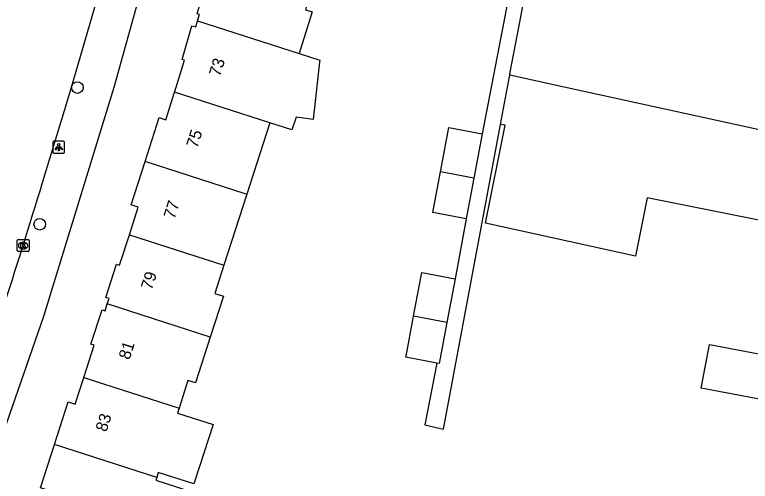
# Model space of a CAD drawing. Extents: x 161402 to 161933, y 381650 to 382313.
# Drawn here: x 161765.1 to 161827.2, y 381716.7 to 381756.1 of the extents above; entities that cross this region are included whole.
import ezdxf

# ---------------------------------------------------------------- set-up
doc = ezdxf.new("R2010")
doc.units = 0
for name, color, linetype in [('IMGEO_Boom', 7, 'Continuous'), ('IMGEO_Kolk', 7, 'Continuous'), ('IMGEO_Lichtpunt', 7, 'Continuous'), ('IMGEO_Pand', 7, 'Continuous'), ('IMGEO_Pand_nummerreeks', 7, 'Continuous'), ('IMGEO_Rijbaan_lokaal_open', 7, 'Continuous'), ('IMGEO_Voetpad_open', 7, 'Continuous')]:
    doc.layers.add(name, color=color, linetype=linetype)

msp = doc.modelspace()

# ---------------------------------------------------------------- linework, layer by layer
at = {"layer": 'IMGEO_Boom'}
for centre in [(161770.361, 381749.955), (161767.179, 381738.411)]:
    msp.add_circle(centre, 0.489, dxfattribs=at)
at = {"layer": 'IMGEO_Kolk'}
for p, q in [((161765.273, 381736.185), (161765.273, 381737.037)), ((161765.348, 381737.111), (161766.2, 381737.111)), ((161765.761, 381736.891), (161765.786, 381736.891)), ((161766.274, 381737.037), (161766.274, 381736.185)), ((161766.2, 381736.111), (161765.348, 381736.111)), ((161765.784, 381736.331), (161765.759, 381736.331))]:
    msp.add_line(p, q, dxfattribs=at)
for points in [[(161765.273, 381736.185), (161765.273, 381737.037)], [(161765.348, 381737.111), (161766.2, 381737.111)], [(161765.594, 381736.811), (161765.717, 381736.811), (161765.717, 381736.66), (161765.847, 381736.811), (161766.011, 381736.811), (161765.865, 381736.66), (161766.018, 381736.411), (161765.866, 381736.411), (161765.781, 381736.575), (161765.717, 381736.508), (161765.717, 381736.411), (161765.594, 381736.411), (161765.594, 381736.811)], [(161766.274, 381737.037), (161766.274, 381736.185)], [(161766.2, 381736.111), (161765.348, 381736.111)]]:
    msp.add_lwpolyline(points, dxfattribs=at)
for centre, start, end in [((161765.35, 381737.035), 91.55205, 178.44795), ((161765.35, 381737.035), 91.55205, 178.44795), ((161766.198, 381737.035), 1.55205, 88.44795), ((161766.198, 381737.035), 1.55205, 88.44795), ((161765.35, 381736.187), 181.55205, 268.44795), ((161765.35, 381736.187), 181.55205, 268.44795), ((161766.198, 381736.187), 271.55205, 358.44795), ((161766.198, 381736.187), 271.55205, 358.44795)]:
    msp.add_arc(centre, 0.0765, start, end, dxfattribs=at)
for centre, major_axis, ratio, start_param, end_param in [((161765.76, 381736.611), (-0.387, 0.002), 0.722429, 4.712389, 7.853982), ((161765.785, 381736.611), (-0.39, 0.002), 0.717154, 1.570796, 4.712389)]:
    msp.add_ellipse(centre, major_axis=major_axis, ratio=ratio, start_param=start_param, end_param=end_param, dxfattribs=at)
at = {"layer": 'IMGEO_Lichtpunt'}
for p, q in [((161769.19, 381745.42), (161768.382, 381745.42)), ((161769.19, 381745.42), (161768.382, 381745.42)), ((161768.288, 381745.325), (161768.288, 381744.518)), ((161768.288, 381745.325), (161768.288, 381744.518)), ((161769.284, 381744.518), (161769.284, 381745.325)), ((161769.284, 381744.518), (161769.284, 381745.325)), ((161768.382, 381744.424), (161769.19, 381744.424)), ((161768.382, 381744.424), (161769.19, 381744.424))]:
    msp.add_line(p, q, dxfattribs=at)
for points in [[(161768.662, 381744.989), (161768.701, 381744.961), (161768.513, 381744.699), (161768.475, 381744.726), (161768.662, 381744.989)], [(161768.764, 381744.941), (161768.811, 381744.941), (161768.811, 381744.619), (161768.764, 381744.619), (161768.764, 381744.941)], [(161768.874, 381744.961), (161768.912, 381744.988), (161769.099, 381744.726), (161769.06, 381744.698), (161768.874, 381744.961)]]:
    msp.add_lwpolyline(points, dxfattribs=at)
msp.add_circle((161768.787, 381745.123), 0.0994, dxfattribs=at)
for centre, start, end in [((161768.382, 381745.325), 90, 180), ((161768.382, 381745.325), 90, 180), ((161769.19, 381745.325), 0, 90), ((161769.19, 381745.325), 0, 90), ((161768.382, 381744.518), 180, 270), ((161768.382, 381744.518), 180, 270), ((161769.19, 381744.518), 270, 0), ((161769.19, 381744.518), 270, 360)]:
    msp.add_arc(centre, 0.0946, start, end, dxfattribs=at)
at = {"layer": 'IMGEO_Pand'}
for points in [[(161806.895, 381751.005), (161806.917, 381751.12), (161807.718, 381755.345), (161809.872, 381766.703), (161809.949, 381766.688)], [(161780.514, 381755.591), (161780.671, 381756.137), (161780.478, 381756.193), (161781.28, 381758.973), (161781.621, 381759.058), (161782.378, 381761.682), (161784.532, 381761.061), (161785.563, 381764.632)], [(161793.752, 381762.268), (161792.555, 381758.12), (161790.297, 381758.772), (161789.646, 381756.516), (161790.187, 381756.36), (161789.103, 381752.824)], [(161778.571, 381749.57), (161778.705, 381750), (161779.408, 381752.261), (161779.216, 381752.316), (161780.042, 381755.179), (161780.368, 381755.085), (161780.514, 381755.591)], [(161780.514, 381755.591), (161789.103, 381752.824)], [(161789.103, 381752.824), (161790.852, 381752.26), (161790.833, 381752.087), (161790.286, 381747.264), (161788.842, 381747.448), (161788.495, 381746.372), (161786.62, 381746.976)], [(161806.126, 381746.844), (161806.71, 381750), (161806.895, 381751.005)], [(161848.392, 381742.544), (161834.903, 381745.106), (161827.854, 381746.416), (161811.485, 381750), (161806.895, 381751.005)], [(161776.082, 381743.713), (161777.28, 381747.426), (161777.848, 381747.243), (161778.571, 381749.57)], [(161786.62, 381746.976), (161778.571, 381749.57)], [(161786.62, 381746.976), (161784.677, 381740.95)], [(161846.453, 381731.901), (161841.538, 381732.82), (161832.077, 381734.588), (161832.719, 381737.797), (161818.513, 381740.64), (161817.529, 381735.723), (161804.849, 381738.517), (161806.502, 381746.774), (161806.126, 381746.844)], [(161801.034, 381742.846), (161801.742, 381746.574), (161804.575, 381746.036)], [(161804.575, 381746.036), (161803.867, 381742.308)], [(161774.751, 381737.528), (161775.499, 381739.845), (161774.897, 381740.039), (161776.082, 381743.713)], [(161784.677, 381740.95), (161784.544, 381740.986), (161776.082, 381743.713)], [(161803.216, 381738.88), (161800.383, 381739.418), (161801.034, 381742.846)], [(161803.867, 381742.308), (161801.034, 381742.846)], [(161803.867, 381742.308), (161803.216, 381738.88)], [(161784.677, 381740.95), (161782.743, 381734.953)], [(161772.89, 381731.69), (161773.037, 381732.146), (161772.774, 381732.231), (161773.679, 381735.039), (161773.923, 381734.96), (161774.751, 381737.528)], [(161774.751, 381737.528), (161782.743, 381734.953)], [(161782.743, 381734.953), (161781.972, 381732.563), (161782.703, 381732.327), (161781.593, 381728.886)], [(161798.773, 381730.66), (161799.474, 381734.349), (161802.287, 381733.814)], [(161802.287, 381733.814), (161801.587, 381730.126)], [(161770.897, 381725.48), (161771.771, 381728.19), (161771.51, 381728.274), (161772.452, 381731.192), (161772.704, 381731.111), (161772.89, 381731.69)], [(161781.593, 381728.886), (161772.89, 381731.69)], [(161800.736, 381726.677), (161798.111, 381727.175), (161798.13, 381727.275), (161798.773, 381730.66)], [(161801.587, 381730.126), (161798.773, 381730.66)], [(161801.587, 381730.126), (161800.925, 381726.641), (161800.736, 381726.677)], [(161820.996, 381694.433), (161821.755, 381698.436), (161824.188, 381697.974), (161825.224, 381703.428), (161827.019, 381703.087), (161830.821, 381723.103), (161823.085, 381724.572), (161823.785, 381728.257), (161831.52, 381726.788), (161832.066, 381729.665), (161840.41, 381728.097), (161845.322, 381727.164)], [(161781.593, 381728.886), (161780.347, 381725.02), (161779.707, 381725.227), (161778.951, 381722.883)], [(161768.436, 381719.817), (161769.594, 381723.408), (161770.168, 381723.222), (161770.897, 381725.48)], [(161770.897, 381725.48), (161778.951, 381722.883)], [(161778.951, 381722.883), (161778.817, 381722.468), (161781.826, 381721.497), (161780.266, 381716.653), (161780.21, 381716.479), (161777.199, 381717.451), (161777.065, 381717.036)], [(161767.099, 381713.662), (161767.841, 381715.963), (161767.254, 381716.152), (161768.436, 381719.817)], [(161777.065, 381717.036), (161768.436, 381719.817)], [(161777.065, 381717.036), (161776.985, 381716.789), (161779.765, 381715.893), (161779.609, 381715.41), (161780.015, 381715.279), (161778.354, 381710.13), (161777.971, 381710.254), (161777.809, 381709.753), (161775.008, 381710.656)]]:
    msp.add_lwpolyline(points, dxfattribs=at)
at = {"layer": 'IMGEO_Rijbaan_lokaal_open'}
msp.add_lwpolyline([(161767.418, 381741.929), (161769.386, 381748.371), (161769.877, 381750), (161773.885, 381763.815)], dxfattribs=at)
msp.add_arc((161210.71, 381911.237), 581.883, 340.83641, 343.084251, dxfattribs=at)
at = {"layer": 'IMGEO_Voetpad_open'}
for points in [[(161774.933, 381686.404), (161758.095, 381688.61), (161755.465, 381688.954), (161753.951, 381692.163), (161755.462, 381695.988), (161767.515, 381730.653), (161773.48, 381750), (161778.317, 381767.408)], [(161793.752, 381762.268), (161793.961, 381762.994), (161807.111, 381759.198), (161804.575, 381746.036)], [(161800.736, 381726.677), (161799.716, 381721.472), (161801.301, 381721.11), (161806.126, 381746.844)], [(161803.216, 381738.88), (161802.287, 381733.814)]]:
    msp.add_lwpolyline(points, dxfattribs=at)

# ---------------------------------------------------------------- texts
at = {"layer": 'IMGEO_Pand_nummerreeks'}
for s, rotation, p in [('73', 72.55365, (161782.405, 381750.827)), ('75', 72.25415, (161780.484, 381744.787)), ('77', 72.25415, (161778.566, 381738.793)), ('79', 72.25415, (161776.648, 381732.8)), ('81', 72.25415, (161774.764, 381726.915)), ('83', 72.25571, (161772.812, 381720.813))]:
    msp.add_text(s, height=1, rotation=rotation, dxfattribs=at).set_placement(p)

doc.saveas('drawing.dxf')
